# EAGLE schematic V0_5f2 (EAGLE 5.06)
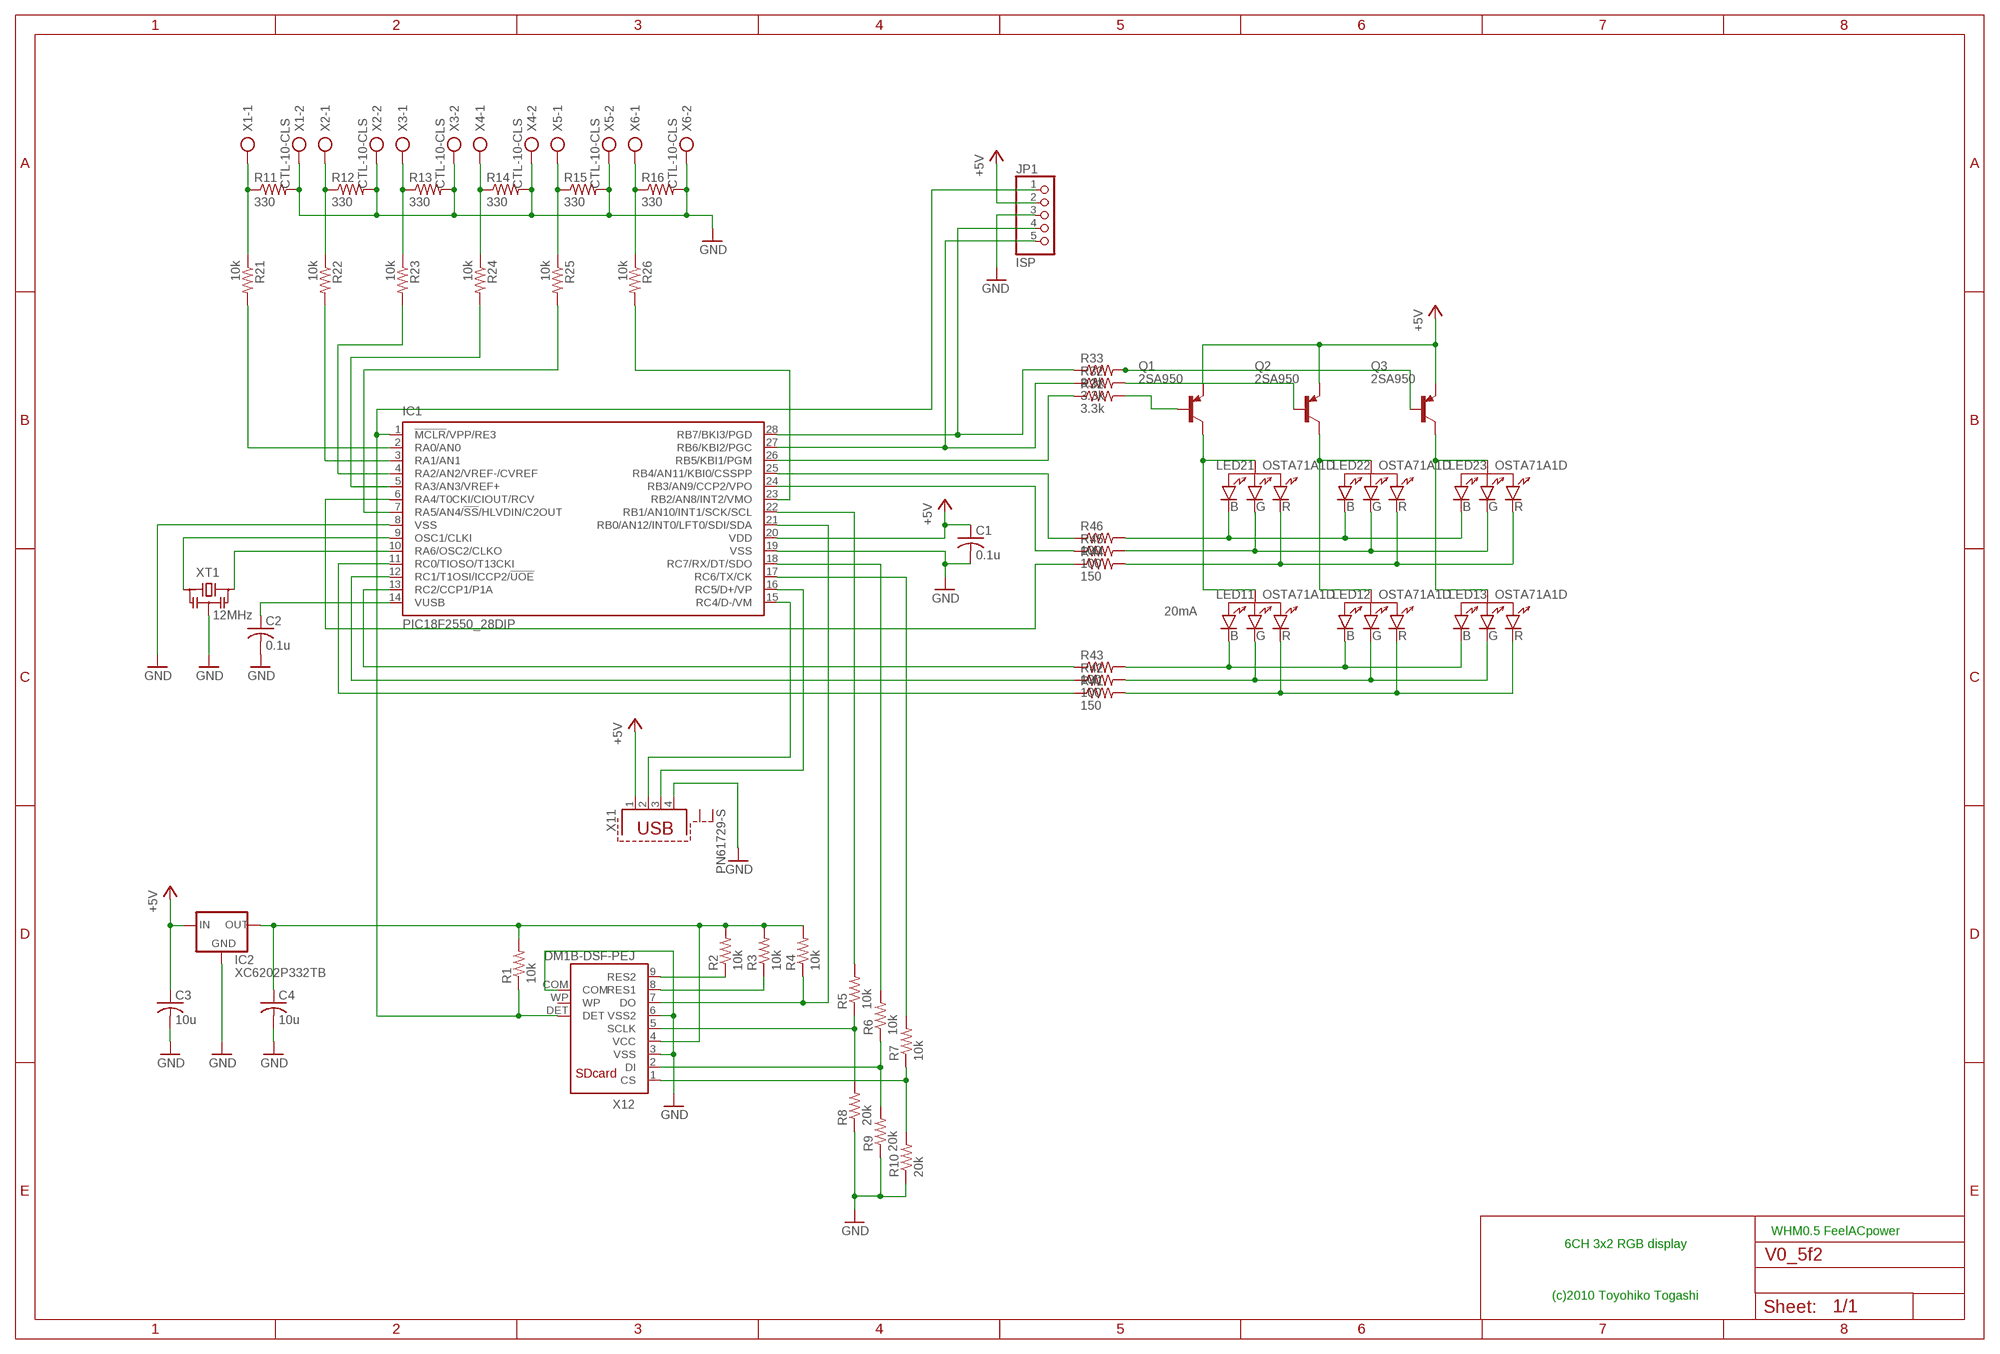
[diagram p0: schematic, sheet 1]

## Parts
C1  0.1u  C-US025-025X050  [C025-025X050]
C2  0.1u  C-US025-025X050  [C025-025X050]
C3  10u  C-US025-025X050  [C025-025X050]
C4  10u  C-US025-025X050  [C025-025X050]
IC1  PIC18F2550_28DIP  [DIL28-3]
IC2  XC6202P332TB  78LXX  [78LXX]
JP1  ISP  PINHD-1X5  [1X05]
LED11  OSTA71A1D  [FLUX-LED]
LED12  OSTA71A1D  [FLUX-LED]
LED13  OSTA71A1D  [FLUX-LED]
LED21  OSTA71A1D  [FLUX-LED]
LED22  OSTA71A1D  [FLUX-LED]
LED23  OSTA71A1D  [FLUX-LED]
Q1  2SA950  BF421  [TO92-BCE]
Q2  2SA950  BF421  [TO92-BCE]
Q3  2SA950  BF421  [TO92-BCE]
R1  10k  R-US_0204/7  [0204/7]
R2  10k  R-US_0204/7  [0204/7]
R3  10k  R-US_0204/7  [0204/7]
R4  10k  R-US_0204/7  [0204/7]
R5  10k  R-US_0204/7  [0204/7]
R6  10k  R-US_0204/7  [0204/7]
R7  10k  R-US_0204/7  [0204/7]
R8  20k  R-US_0204/7  [0204/7]
R9  20k  R-US_0204/7  [0204/7]
R10  20k  R-US_0204/7  [0204/7]
R11  330  R-US_0204/7  [0204/7]
R12  330  R-US_0204/7  [0204/7]
R13  330  R-US_0204/7  [0204/7]
R14  330  R-US_0204/7  [0204/7]
R15  330  R-US_0204/7  [0204/7]
R16  330  R-US_0204/7  [0204/7]
R21  10k  R-US_0204/7  [0204/7]
R22  10k  R-US_0204/7  [0204/7]
R23  10k  R-US_0204/7  [0204/7]
R24  10k  R-US_0204/7  [0204/7]
R25  10k  R-US_0204/7  [0204/7]
R26  10k  R-US_0204/7  [0204/7]
R31  3.3k  R-US_0204/7  [0204/7]
R32  3.3k  R-US_0204/7  [0204/7]
R33  3.3k  R-US_0204/7  [0204/7]
R41  150  R-US_0204/7  [0204/7]
R42  100  R-US_0204/7  [0204/7]
R43  100  R-US_0204/7  [0204/7]
R44  150  R-US_0204/5  [0204/5]
R45  100  R-US_0204/5  [0204/5]
R46  100  R-US_0204/5  [0204/5]
X1  CTL-10-CLS  AK500/2  [AK500/2]
X2  CTL-10-CLS  AK500/2  [AK500/2]
X3  CTL-10-CLS  AK500/2  [AK500/2]
X4  CTL-10-CLS  AK500/2  [AK500/2]
X5  CTL-10-CLS  AK500/2  [AK500/2]
X6  CTL-10-CLS  AK500/2  [AK500/2]
X11  PN61729-S  [PN61729-S]
X12  DM1B-DSF-PEJ  [DM1B]
XT1  12MHz  CSTLS  [S3P]

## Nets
+5V: C1.1 C3.1 IC1.20(VDD) IC2.IN JP1.2 Q1.E Q2.E Q3.E X11.1
GND: C1.2 C2.2 C3.2 C4.2 IC1.8(VSS) IC1.19(VSS) IC2.GND JP1.3 R8.1 R9.1 R10.1 R11.2 R12.2 R13.2 R14.2 R15.2 R16.2 X1.2 X2.2 X3.2 X4.2 X5.2 X6.2 X11.4 X12.3(VSS) X12.6(VSS2) X12.COM XT1.P$2
N$1: IC1.7(RA5/AN4/!SS!/HLVDIN/C2OUT) R25.2
N$2: IC1.5(RA3/AN3/VREF+) R24.2
N$3: IC1.4(RA2/AN2/VREF-/CVREF) R23.2
N$4: IC1.3(RA1/AN1) R22.2
N$5: C4.1 IC2.OUT R1.2 R2.2 R3.2 R4.2 X12.4(VCC)
N$6: R5.1 R8.2 X12.5(SCLK)
N$7: IC1.21(RB0/AN12/INT0/LFT0/SDI/SDA) R4.1 X12.7(DO)
N$8: R6.1 R9.2 X12.2(DI)
N$9: R7.1 R10.2 X12.1(CS)
N$10: IC1.1(!MCLR!/VPP/RE3) JP1.1 R1.1 X12.DET
N$12: LED21.P$2 LED22.P$2 LED23.P$2 R46.2
N$14: IC1.25(RB4/AN11/KBI0/CSSPP) R46.1
N$15: LED12.P$1 LED22.P$1 Q2.C
N$16: IC1.15(RC4/D-/VM) X11.2
N$17: IC1.16(RC5/D+/VP) X11.3
N$18: LED13.P$1 LED23.P$1 Q3.C
N$20: IC1.22(RB1/AN10/INT1/SCK/SCL) R5.2
N$21: IC1.18(RC7/RX/DT/SDO) R6.2
N$22: IC1.17(RC6/TX/CK) R7.2
N$23: IC1.6(RA4/T0CKI/CIOUT/RCV) R44.1
N$25: IC1.11(RC0/TIOSO/T13CKI) R41.1
N$26: IC1.26(RB5/KBI1/PGM) R31.1
N$27: IC1.12(RC1/T1OSI/ICCP2/!UOE) R42.1
N$28: IC1.13(RC2/CCP1/P1A) R43.1
N$29: IC1.23(RB2/AN8/INT2/VMO) R26.2
N$30: IC1.28(RB7/BKI3/PGD) JP1.4 R33.1
N$31: IC1.27(RB6/KBI2/PGC) JP1.5 R32.1
N$32: LED21.P$3 LED22.P$3 LED23.P$3 R45.2
N$33: Q1.B R31.2
N$34: LED21.P$4 LED22.P$4 LED23.P$4 R44.2
N$35: Q2.B R32.2
N$37: R16.1 R26.1 X6.1
N$38: R15.1 R25.1 X5.1
N$39: R14.1 R24.1 X4.1
N$40: R13.1 R23.1 X3.1
N$41: R12.1 R22.1 X2.1
N$42: R2.1 X12.9(RES2)
N$43: R3.1 X12.8(RES1)
N$44: R11.1 R21.1 X1.1
N$45: Q3.B R33.2
N$47: IC1.10(RA6/OSC2/CLKO) XT1.P$3
N$49: IC1.9(OSC1/CLKI) XT1.P$1
N$50: IC1.2(RA0/AN0) R21.2
N$52: C2.1 IC1.14(VUSB)
N$55: LED11.P$1 LED21.P$1 Q1.C
N$56: LED11.P$2 LED12.P$2 LED13.P$2 R43.2
N$58: LED11.P$4 LED12.P$4 LED13.P$4 R41.2
N$59: LED11.P$3 LED12.P$3 LED13.P$3 R42.2
N$65: IC1.24(RB3/AN9/CCP2/VPO) R45.1
Unconnected: X11.S1 X11.S2 X12.WP

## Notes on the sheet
- 20mA
- WHM0.5 FeelACpower
- 6CH 3x2 RGB display
- (c)2010 Toyohiko Togashi

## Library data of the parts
C1-C4 = rcl:C-US: CAPACITOR, American symbol
IC1 = microchip:PIC18F2*_28: USB Microcontrollers with nanoWatt Technology High-Performance, Enhanced Flash, 28/40/44-Pin, Source: http://ww1.microchip.com/downloads/en/devicedoc/39632c.pdf
IC2 = v-reg:78LXX: VOLTAGE REGULATOR
JP1 = pinhead:PINHD-1X5: PIN HEADER
LED11-LED13 LED21-LED23 = TOG:OSTA71A1D: Super Flux RGB LED
Q1-Q3 = transistor-pnp:BF421*: PNP Transistror
R1-R16 R21-R26 R31-R33 R41-R46 = rcl:R-US_: RESISTOR, American symbol
X1-X6 = con-ptr500:AK500/2: CONNECTOR
X11 = con-berg:PN61729-S: BERG USB connector
X12 = TOG:DM1B-DSF-PEJ: SDcard connector reverse type HIROSE
XT1 = TOG:CSTLS: Resonator, Murata Ceralock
